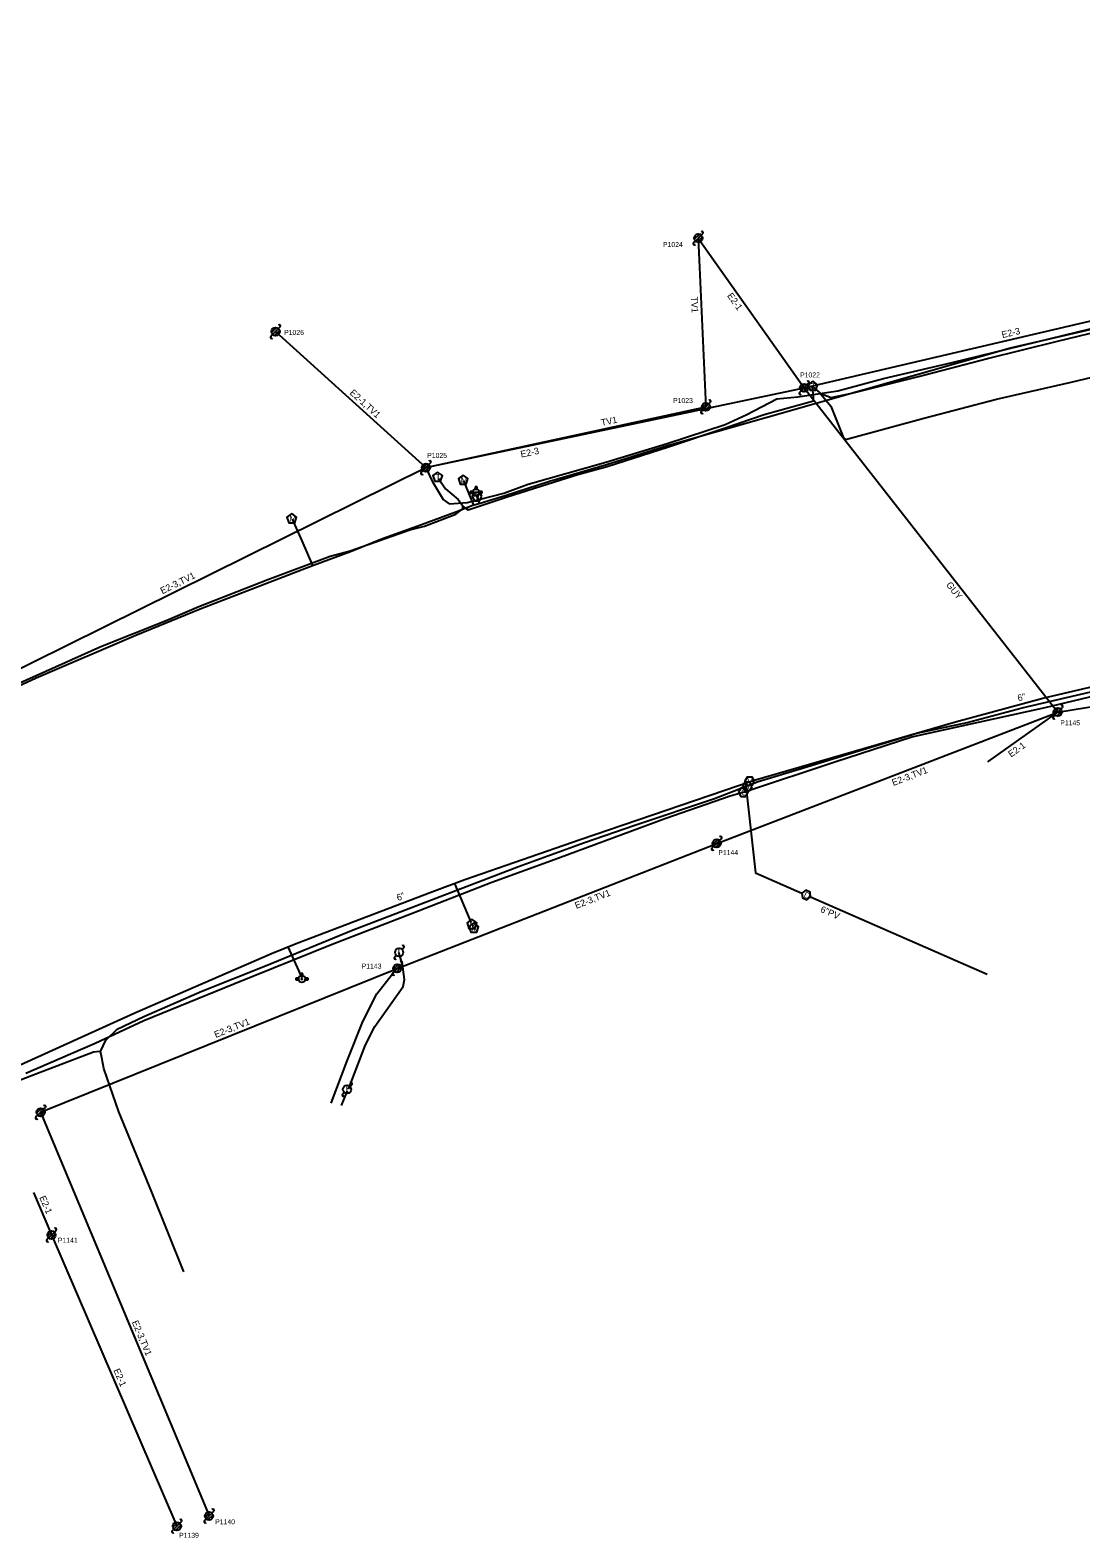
# Model space of a CAD drawing. Extents: x 1741604 to 1825760, y 1164229 to 1194908.
# Drawn here: x 1807205 to 1807840, y 1189313 to 1190224 of the extents above; entities that cross this region are included whole.
import ezdxf

# ---------------------------------------------------------------- set-up
doc = ezdxf.new("R2010")
doc.units = 0
for name, color, linetype in [('RD_EX_SU_Elec', 7, 'Continuous'), ('RD_EX_SU_Gas', 7, 'Continuous'), ('RD_EX_SU_H2O', 7, 'Continuous'), ('RD_EX_SU_Ovhd', 7, 'Continuous'), ('RD_EX_SU_Pole', 7, 'Continuous'), ('RD_EX_SU_Telecom', 7, 'Continuous'), ('RD_EX_SU_TX_H2O', 7, 'Continuous'), ('RD_EX_SU_TX_Pole', 7, 'Continuous')]:
    doc.layers.add(name, color=color, linetype=linetype)

# ---------------------------------------------------------------- blocks, each defined once
blk = doc.blocks.new('SUE_TPP')
at = {"layer": 'RD_EX_SU_Telecom'}
blk.add_lwpolyline([(0, 3), (-2.85, 0.93), (-1.76, -2.43), (1.76, -2.43), (2.85, 0.93)], close=True, dxfattribs=at)
blk.add_text('T', height=3.75, dxfattribs=at).set_placement((-1.25, -1.88))
blk = doc.blocks.new('SUE_WFH')
at = {"layer": 'RD_EX_SU_H2O'}
for p, q in [((-2.01, 0.6), (-3.65, 0.6)), ((-3.65, 0.6), (-3.65, -0.45)), ((-0.48, 3.38), (-0.48, 2.04)), ((0.57, 3.38), (-0.48, 3.38)), ((0.57, 2.02), (0.57, 3.38)), ((3.7, 0.6), (2.01, 0.6)), ((3.7, -0.45), (3.7, 0.6)), ((-3.65, -0.45), (-2.05, -0.45)), ((2.05, -0.45), (3.7, -0.45))]:
    blk.add_line(p, q, dxfattribs=at)
for radius in [2.1, 0.263]:
    blk.add_circle((0, 0), radius, dxfattribs=at)
for start, end in [(163.3387, 192.31502), (74.24552, 103.21276), (347.68498, 16.6613)]:
    blk.add_arc((0, 0), 2.1, start, end, dxfattribs=at)
blk = doc.blocks.new('SUE_WV')
at = {"layer": 'RD_EX_SU_H2O'}
blk.add_lwpolyline([(2.89, 0), (1.44, 2.5), (-1.44, 2.5), (-2.89, 0), (-1.44, -2.5), (1.44, -2.5)], close=True, dxfattribs=at)
blk.add_text('V', height=3.75, dxfattribs=at).set_placement((-1.43, -1.88))
blk = doc.blocks.new('SUE_WM')
at = {"layer": 'RD_EX_SU_H2O'}
blk.add_lwpolyline([(0, 3.05), (-2.9, 0.94), (-1.79, -2.47), (1.79, -2.47), (2.9, 0.94)], close=True, dxfattribs=at)
blk.add_text('M', height=3.75, dxfattribs=at).set_placement((-1.43, -1.88))
blk = doc.blocks.new('SUE_GVC')
at = {"layer": 'RD_EX_SU_Gas'}
blk.add_lwpolyline([(1.44, -2.5), (2.89, 0), (1.44, 2.5), (-1.44, 2.5), (-2.89, 0), (-1.44, -2.5)], close=True, dxfattribs=at)
blk.add_text('G', height=3.75, dxfattribs=at).set_placement((-1.34, -1.88))
blk = doc.blocks.new('SUE_PP')
at = {"layer": 'RD_EX_SU_Pole'}
for p, q in [((-2.41, -0.65), (0.65, 2.41)), ((-1.77, -1.77), (1.77, 1.77)), ((-0.65, -2.41), (2.41, 0.65)), ((1.77, 1.77), (2.83, 2.83)), ((-2.83, -2.83), (-1.77, -1.77))]:
    blk.add_line(p, q, dxfattribs=at)
blk.add_circle((0, 0), 2.5, dxfattribs=at)
for centre, start, end in [((2.3, 3.36), 315, 135), ((-2.3, -3.36), 135, 315)]:
    blk.add_arc(centre, 0.75, start, end, dxfattribs=at)

msp = doc.modelspace()

# ---------------------------------------------------------------- linework, layer by layer
at = {"layer": 'RD_EX_SU_Elec'}
msp.add_line((1807396.79, 1189583.14), (1807393.06, 1189574.26), dxfattribs=at)
for points in [[(1807397.53, 1189584.19), (1807407.84, 1189610.89), (1807413.51, 1189622.09), (1807430.6, 1189646.23), (1807431.32, 1189650.41), (1807430.25, 1189659.4), (1807428, 1189666.79)], [(1807387.03, 1189575.61), (1807396.75, 1189601.17), (1807406.1, 1189624.97), (1807414.64, 1189641.75), (1807426.36, 1189656.68)]]:
    msp.add_lwpolyline(points, dxfattribs=at)
at = {"layer": 'RD_EX_SU_Gas'}
msp.add_lwpolyline([(1807202.55, 1189593.86), (1807244.4, 1189612.02), (1807273.79, 1189625.62), (1807328.26, 1189647.9), (1807387.74, 1189671.88), (1807435.65, 1189690.41), (1807484.25, 1189709.27), (1807520.29, 1189722.4), (1807589.39, 1189747.97), (1807628.2, 1189761.41), (1807638.08, 1189764.18), (1807691.6, 1189781.97), (1807738, 1189797.04), (1807818.59, 1189814.89), (1807892.2, 1189832.29)], dxfattribs=at)
at = {"layer": 'RD_EX_SU_H2O'}
for p, q in [((1807467.01, 1189951.9), (1807473.15, 1189937.24)), ((1807476.63, 1189938.25), (1807475.07, 1189943.77)), ((1807448, 1189703.51), (1807467.81, 1189710.86)), ((1807461.59, 1189708.55), (1807471.51, 1189685.07)), ((1807365.89, 1189672.21), (1807448, 1189703.51)), ((1807351.06, 1189666.17), (1807365.89, 1189672.21)), ((1807360.82, 1189670.14), (1807369.24, 1189651.45))]:
    msp.add_line(p, q, dxfattribs=at)
for points in [[(1807590.47, 1189973.29), (1807797.74, 1190032.28), (1807994.63, 1190077.48)], [(1806907.43, 1189689.88), (1806921.87, 1189696.65), (1806956.44, 1189714.06), (1806994.25, 1189732.8), (1807032.97, 1189751.74), (1807070.31, 1189769.86), (1807107.76, 1189786.85), (1807128.65, 1189797.57), (1807158.71, 1189809.89), (1807208.73, 1189832.68), (1807268.98, 1189858.51), (1807307.86, 1189874.46), (1807369.48, 1189898.22), (1807376.36, 1189900.86), (1807398.77, 1189909.06), (1807418.17, 1189917), (1807441.66, 1189925.38), (1807462.45, 1189933.1), (1807472.72, 1189937.12), (1807477.17, 1189938.4), (1807492.18, 1189942.96), (1807518.95, 1189951.71), (1807553.46, 1189961.82), (1807590.47, 1189973.29)], [(1807363.39, 1189928.67), (1807369.4, 1189915.61), (1807375.83, 1189900.65)], [(1807642.08, 1189770.78), (1807764.43, 1189806.14), (1807817.32, 1189820.38), (1807994.06, 1189861.76), (1808053.5, 1189874.9), (1808100.62, 1189884.58)], [(1807467.81, 1189710.86), (1807537.66, 1189735.05), (1807642.08, 1189770.78)], [(1807637.49, 1189769.21), (1807643.66, 1189714.86), (1807671.58, 1189702.66)], [(1807676.87, 1189700.35), (1807783.7, 1189653.66)], [(1807054.08, 1189530.73), (1807151.37, 1189577.28), (1807268.33, 1189630.19), (1807351.06, 1189666.17)]]:
    msp.add_lwpolyline(points, dxfattribs=at)
msp.add_lwpolyline([(1807676.87, 1189700.35), (1807676.55, 1189703.22), (1807673.91, 1189704.37), (1807671.58, 1189702.66), (1807671.9, 1189699.79), (1807674.55, 1189698.64)], close=True, dxfattribs=at)
at = {"layer": 'RD_EX_SU_Ovhd'}
for p, q in [((1807608.98, 1190098.57), (1807613.61, 1189996.58)), ((1807608.98, 1190098.57), (1807672.95, 1190008.06)), ((1807672.95, 1190008.06), (1807936.63, 1190069.59)), ((1807353.44, 1190042.07), (1807444.37, 1189959.86)), ((1807444.37, 1189959.86), (1807672.95, 1190008.06)), ((1807672.95, 1190008.06), (1807826.32, 1189812.08)), ((1807444.37, 1189959.86), (1807613.61, 1189996.58)), ((1807094.17, 1189786.71), (1807444.37, 1189959.86)), ((1807826.32, 1189812.08), (1808143.68, 1189862.89)), ((1807620.11, 1189732.69), (1807826.32, 1189812.08)), ((1807784.1, 1189781.91), (1807826.32, 1189812.08)), ((1807427.04, 1189657.16), (1807620.11, 1189732.69)), ((1807211.44, 1189570.19), (1807427.04, 1189657.16)), ((1807211.43, 1189570.2), (1807313.24, 1189326.14)), ((1807207.07, 1189521.76), (1807217.98, 1189496.02)), ((1807217.98, 1189496.02), (1807293.8, 1189319.95))]:
    msp.add_line(p, q, dxfattribs=at)
at = {"layer": 'RD_EX_SU_Pole'}
for p, q in [((1807606.15, 1190095.74), (1807607.21, 1190096.8)), ((1807606.56, 1190097.92), (1807609.63, 1190100.99)), ((1807607.21, 1190096.8), (1807610.75, 1190100.34)), ((1807608.33, 1190096.16), (1807611.39, 1190099.22)), ((1807610.75, 1190100.34), (1807611.81, 1190101.4)), ((1807670.12, 1190005.23), (1807671.18, 1190006.29)), ((1807670.53, 1190007.41), (1807673.59, 1190010.48)), ((1807671.18, 1190006.29), (1807674.71, 1190009.83)), ((1807672.3, 1190005.65), (1807675.36, 1190008.71)), ((1807674.71, 1190009.83), (1807675.78, 1190010.89)), ((1807611.19, 1189995.93), (1807614.26, 1189999)), ((1807611.84, 1189994.81), (1807615.38, 1189998.35)), ((1807612.96, 1189994.17), (1807616.02, 1189997.23)), ((1807615.38, 1189998.35), (1807616.44, 1189999.41)), ((1807610.78, 1189993.75), (1807611.84, 1189994.81)), ((1807441.96, 1189959.22), (1807445.02, 1189962.28)), ((1807442.61, 1189958.1), (1807446.14, 1189961.63)), ((1807443.73, 1189957.45), (1807446.79, 1189960.51)), ((1807446.14, 1189961.63), (1807447.2, 1189962.69)), ((1807441.55, 1189957.03), (1807442.61, 1189958.1)), ((1807823.91, 1189811.43), (1807826.97, 1189814.49)), ((1807828.09, 1189813.84), (1807829.15, 1189814.9)), ((1807823.49, 1189809.25), (1807824.55, 1189810.31)), ((1807824.55, 1189810.31), (1807828.09, 1189813.84)), ((1807825.67, 1189809.66), (1807828.74, 1189812.72)), ((1807617.69, 1189732.04), (1807620.75, 1189735.1)), ((1807618.34, 1189730.92), (1807621.87, 1189734.45)), ((1807619.46, 1189730.27), (1807622.52, 1189733.33)), ((1807621.87, 1189734.45), (1807622.94, 1189735.51)), ((1807617.28, 1189729.86), (1807618.34, 1189730.92)), ((1807429.93, 1189668.6), (1807431, 1189669.66)), ((1807424.63, 1189656.51), (1807427.69, 1189659.57)), ((1807425.34, 1189664), (1807426.4, 1189665.06)), ((1807428.81, 1189658.93), (1807429.87, 1189659.99)), ((1807424.21, 1189654.33), (1807425.27, 1189655.39)), ((1807425.27, 1189655.39), (1807428.81, 1189658.93)), ((1807426.39, 1189654.74), (1807429.46, 1189657.81)), ((1807398.47, 1189585.78), (1807399.54, 1189586.84)), ((1807393.88, 1189581.19), (1807394.94, 1189582.25)), ((1807208.61, 1189567.36), (1807209.67, 1189568.42)), ((1807209.02, 1189569.55), (1807212.09, 1189572.61)), ((1807209.67, 1189568.42), (1807213.21, 1189571.96)), ((1807210.79, 1189567.78), (1807213.85, 1189570.84)), ((1807213.21, 1189571.96), (1807214.27, 1189573.02))]:
    msp.add_line(p, q, dxfattribs=at)
for centre in [(1807608.98, 1190098.57), (1807672.95, 1190008.06), (1807613.61, 1189996.58), (1807444.37, 1189959.86), (1807826.32, 1189812.08), (1807620.11, 1189732.69), (1807428.17, 1189666.83), (1807427.04, 1189657.16), (1807396.71, 1189584.02), (1807211.44, 1189570.19)]:
    msp.add_circle(centre, 2.5, dxfattribs=at)
for centre, start, end in [((1807611.28, 1190101.93), 315, 135), ((1807606.68, 1190095.21), 135, 315), ((1807675.25, 1190011.42), 315, 135), ((1807615.91, 1189999.94), 315, 135), ((1807670.65, 1190004.7), 135, 315), ((1807611.31, 1189993.22), 135, 315), ((1807446.67, 1189963.22), 315, 135), ((1807442.08, 1189956.5), 135, 315), ((1807828.62, 1189815.43), 315, 135), ((1807824.02, 1189808.72), 135, 315), ((1807622.41, 1189736.04), 315, 135), ((1807617.81, 1189729.33), 135, 315), ((1807430.47, 1189670.19), 315, 135), ((1807425.87, 1189663.47), 135, 315), ((1807429.34, 1189660.52), 315, 135), ((1807424.74, 1189653.8), 135, 315), ((1807399, 1189587.38), 315, 135), ((1807394.41, 1189580.66), 135, 315), ((1807213.74, 1189573.55), 315, 135), ((1807209.14, 1189566.83), 135, 315)]:
    msp.add_arc(centre, 0.75, start, end, dxfattribs=at)
at = {"layer": 'RD_EX_SU_Telecom'}
for points in [[(1807682.5, 1190004.86), (1807689.27, 1190002.32), (1807701.89, 1190004.93), (1807742.09, 1190014.9), (1807783.79, 1190025.79), (1807826.14, 1190036.18), (1807889.51, 1190051.54), (1807953.85, 1190065.04), (1807974.32, 1190070.37), (1808007.49, 1190077.56), (1808013.57, 1190081.16), (1808017.43, 1190089.5), (1808027.32, 1190095.12), (1808028.05, 1190096.96), (1808027.78, 1190101.02), (1808023.46, 1190126.79), (1808016.98, 1190164.5), (1808006.98, 1190224.27)], [(1807678.17, 1190008.71), (1807682.41, 1190004.96), (1807689.11, 1189996.9), (1807696.72, 1189977.75), (1807698.02, 1189976.79), (1807746.2, 1189989.96), (1807789.33, 1190001.12), (1807834.33, 1190011.55), (1807879.26, 1190022.08), (1807923.16, 1190032.03), (1807967.55, 1190041.17), (1807996.6, 1190043.46), (1808016.06, 1190044.83), (1808064.17, 1190052.82), (1808135.81, 1190066.49), (1808175.72, 1190072.55), (1808208.14, 1190077.12), (1808224.34, 1190077.5), (1808234.29, 1190073.69)], [(1807444.75, 1189958.89), (1807448.07, 1189951.74), (1807454.82, 1189940.47), (1807458.49, 1189938.01), (1807469.49, 1189938.8), (1807491.5, 1189944.36), (1807506.12, 1189949.89), (1807553.11, 1189963.22), (1807590.09, 1189974.45), (1807625.17, 1189985.92), (1807638.41, 1189992.04), (1807656.49, 1190001.48), (1807669.1, 1190002.7), (1807693.36, 1190006.35), (1807720.9, 1190013.74), (1807762.38, 1190023.34), (1807804.67, 1190033.56), (1807846.62, 1190043.84)], [(1807451.92, 1189953.19), (1807456.24, 1189946.99), (1807463.77, 1189940.51), (1807467.13, 1189936.05), (1807469.88, 1189934.36), (1807492.87, 1189942.01), (1807518.24, 1189950.04), (1807536.2, 1189955.64), (1807553.99, 1189960.56), (1807591.02, 1189972.35), (1807625.75, 1189984.05), (1807648.79, 1189991.89), (1807678.57, 1190000.25), (1807678.72, 1190003.76), (1807677.75, 1190008.65)], [(1806904.55, 1189692.54), (1806906.54, 1189692.06), (1806920.67, 1189698.38), (1806940.27, 1189707.91), (1806972.42, 1189723.75), (1807010.25, 1189742.6), (1807051.28, 1189762.56), (1807089.91, 1189780.61), (1807119.1, 1189796.65), (1807136.71, 1189803.97), (1807145.05, 1189805.3), (1807173.1, 1189818.28), (1807208.66, 1189834.24), (1807247.85, 1189851.63), (1807287.35, 1189867.48), (1807307.05, 1189875.88), (1807348.87, 1189892.28), (1807386.47, 1189906.36), (1807398.63, 1189909.48), (1807434.55, 1189922.3), (1807443.51, 1189924.38), (1807462.38, 1189931.66), (1807466.63, 1189934.89), (1807466.75, 1189936.55)], [(1807297.92, 1189473.8), (1807278.62, 1189521.83), (1807258.78, 1189570.48), (1807249.72, 1189596.68), (1807248.4, 1189603), (1807247.52, 1189606.94), (1807250.87, 1189613.72), (1807257.72, 1189620.43), (1807273.89, 1189628.12), (1807308.81, 1189643.37), (1807347.37, 1189658.6), (1807400.32, 1189680.47), (1807450.38, 1189699.52), (1807500.38, 1189718.76), (1807540.17, 1189733.15), (1807570.54, 1189743.69), (1807618.79, 1189759.82), (1807645.17, 1189770.03), (1807671.99, 1189778.24), (1807705.97, 1189788.55), (1807741.2, 1189799.36), (1807771.63, 1189805.79), (1807804.88, 1189814.7), (1807852.38, 1189825.77)], [(1807003.98, 1189490.66), (1807002.64, 1189495.29), (1807002.36, 1189497.76), (1807009.44, 1189502.95), (1807050.21, 1189525.6), (1807090.24, 1189545.85), (1807128.99, 1189564.14), (1807166.58, 1189577.34), (1807208.43, 1189593.43), (1807243.47, 1189606.68), (1807247.15, 1189607.1), (1807247.52, 1189606.94)]]:
    msp.add_lwpolyline(points, dxfattribs=at)

# ---------------------------------------------------------------- block references
at = {"layer": 'RD_EX_SU_Gas'}
msp.add_blockref('SUE_GVC', (1807636.22, 1189763.59), dxfattribs=at)
at = {"layer": 'RD_EX_SU_H2O'}
for name, p in [('SUE_WM', (1807466.86, 1189952.31)), ('SUE_WFH', (1807474.66, 1189944.8)), ('SUE_WV', (1807475.2, 1189942.34)), ('SUE_WM', (1807363.21, 1189928.99)), ('SUE_WV', (1807638.64, 1189767.11)), ('SUE_WV', (1807640.03, 1189770.3)), ('SUE_WM', (1807472.17, 1189683.77)), ('SUE_WM', (1807473.24, 1189681.58)), ('SUE_WFH', (1807369.37, 1189650.68))]:
    msp.add_blockref(name, p, dxfattribs=at)
at = {"layer": 'RD_EX_SU_Pole'}
for p in [(1807353.44, 1190042.07), (1807217.98, 1189496.02), (1807293.8, 1189319.95), (1807313.24, 1189326.14)]:
    msp.add_blockref('SUE_PP', p, dxfattribs=at)
at = {"layer": 'RD_EX_SU_Telecom'}
for p in [(1807678.29, 1190009), (1807451.43, 1189954.16)]:
    msp.add_blockref('SUE_TPP', p, dxfattribs=at)

# ---------------------------------------------------------------- texts
at = {"layer": 'RD_EX_SU_H2O'}
msp.add_text('D', height=3.75, rotation=336.39121, dxfattribs=at).set_placement((1807672.33, 1189700.29))
at = {"layer": 'RD_EX_SU_Ovhd'}
for s, rotation, p in [('TV1', 272.59909, (1807604.58, 1190063.13)), ('E2-1', 305.25127, (1807626.25, 1190063.73)), ('E2-3', 13.13504, (1807792.88, 1190038.1)), ('E2-1,TV1', 317.88404, (1807397.9, 1190004.57)), ('TV1', 12.24145, (1807550.65, 1189984.97)), ('E2-3', 11.90739, (1807501.95, 1189965.87)), ('E2-3,TV1', 26.30911, (1807284.98, 1189883.29)), ('GUY', 308.04587, (1807758.59, 1189888.89)), ('E2-1', 35.54511, (1807798.07, 1189784.52)), ('E2-3,TV1', 21.05602, (1807726.92, 1189767.38)), ('E2-3,TV1', 21.36524, (1807535.27, 1189693.06)), ('E2-3,TV1', 21.96753, (1807317.31, 1189615.05)), ('E2-1', 292.96138, (1807210.54, 1189518.7)), ('E2-3,TV1', 292.64376, (1807266.5, 1189443.37)), ('E2-1', 293.29789, (1807255.38, 1189414.23))]:
    msp.add_text(s, height=4, rotation=rotation, dxfattribs=at).set_placement(p)
at = {"layer": 'RD_EX_SU_Pole'}
for p in [(1807427.3, 1189664.83), (1807395.84, 1189582.02)]:
    msp.add_text('L', height=4, dxfattribs=at).set_placement(p)
at = {"layer": 'RD_EX_SU_TX_H2O'}
for s, rotation, p in [('6"', 15.07555, (1807802.54, 1189818.47)), ('6"', 20.87049, (1807427.46, 1189697.82)), ('6"PV', 336.39121, (1807682.36, 1189691.4))]:
    msp.add_text(s, height=4, rotation=rotation, dxfattribs=at).set_placement(p)
at = {"layer": 'RD_EX_SU_TX_Pole'}
for s, p in [('P1024', (1807587.64, 1190093.18)), ('P1026', (1807358.63, 1190040.05)), ('P1022', (1807670.54, 1190014.37)), ('P1023', (1807593.76, 1189998.89)), ('P1025', (1807445.12, 1189965.7)), ('P1145', (1807827.82, 1189804.08)), ('P1144', (1807621.09, 1189725.63)), ('P1143', (1807405.5, 1189657.03)), ('P1141', (1807221.87, 1189491.31)), ('P1140', (1807316.94, 1189321.14)), ('P1139', (1807295.1, 1189312.97))]:
    msp.add_text(s, height=3, dxfattribs=at).set_placement(p)

doc.saveas('drawing.dxf')
